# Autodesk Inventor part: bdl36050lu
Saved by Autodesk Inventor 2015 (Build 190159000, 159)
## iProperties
Created: 2021-08
Part Number: bdl36050lu
Checked By: TraceParts S.A.
Material: Generic
Catalog Web Link: www.traceparts.com
Document SubType Name: Modeling
Designer: TraceParts
Density: 1 g/cm^3
Appearance: Default
Company: TraceParts S.A.
Author: TraceParts
REFERENCE: BDL36050LU
DESIGN: PowerPact BD 600Y/347V TM50D 3P EverLink control wire terminal circuit breaker
SUPPLIER: Schneider Electric
TraceParts.PartNumber: 10-21112016-071385
TraceParts.PartTitle: PowerPact BD/BG/BJ 15A to 125A 3P EverLink control wire terminal circuit breaker
TraceParts.InstanceId: 10-21112016-071385ABO5209GUNAWCPTI3HNQK6U5S
TraceParts.PartStatus: Published
TraceParts.PartVersion: 1.0.1
TRACEPARTS: TRACEPARTS
TraceParts.PartLanguage: en
TraceParts.ClassPath: SCHNEIDER_ELECTRIC_DISTRI:10-21112016-071385
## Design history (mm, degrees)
feature "bdl36050lu_01"
feature "bdl36050lu_02"
feature "bdl36050lu_03"
feature "bdl36050lu_04"
feature "bdl36050lu_05"
feature "bdl36050lu_06"
feature "bdl36050lu_07"
feature "bdl36050lu_08"
feature "bdl36050lu_09"
body "Solid1"
body "Solid2"
body "Solid3"
body "Solid4"
body "Solid5"
body "Solid6"
body "Solid7"
body "Solid8"
body "Solid9"
